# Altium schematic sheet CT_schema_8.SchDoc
size 391 x 238 mm
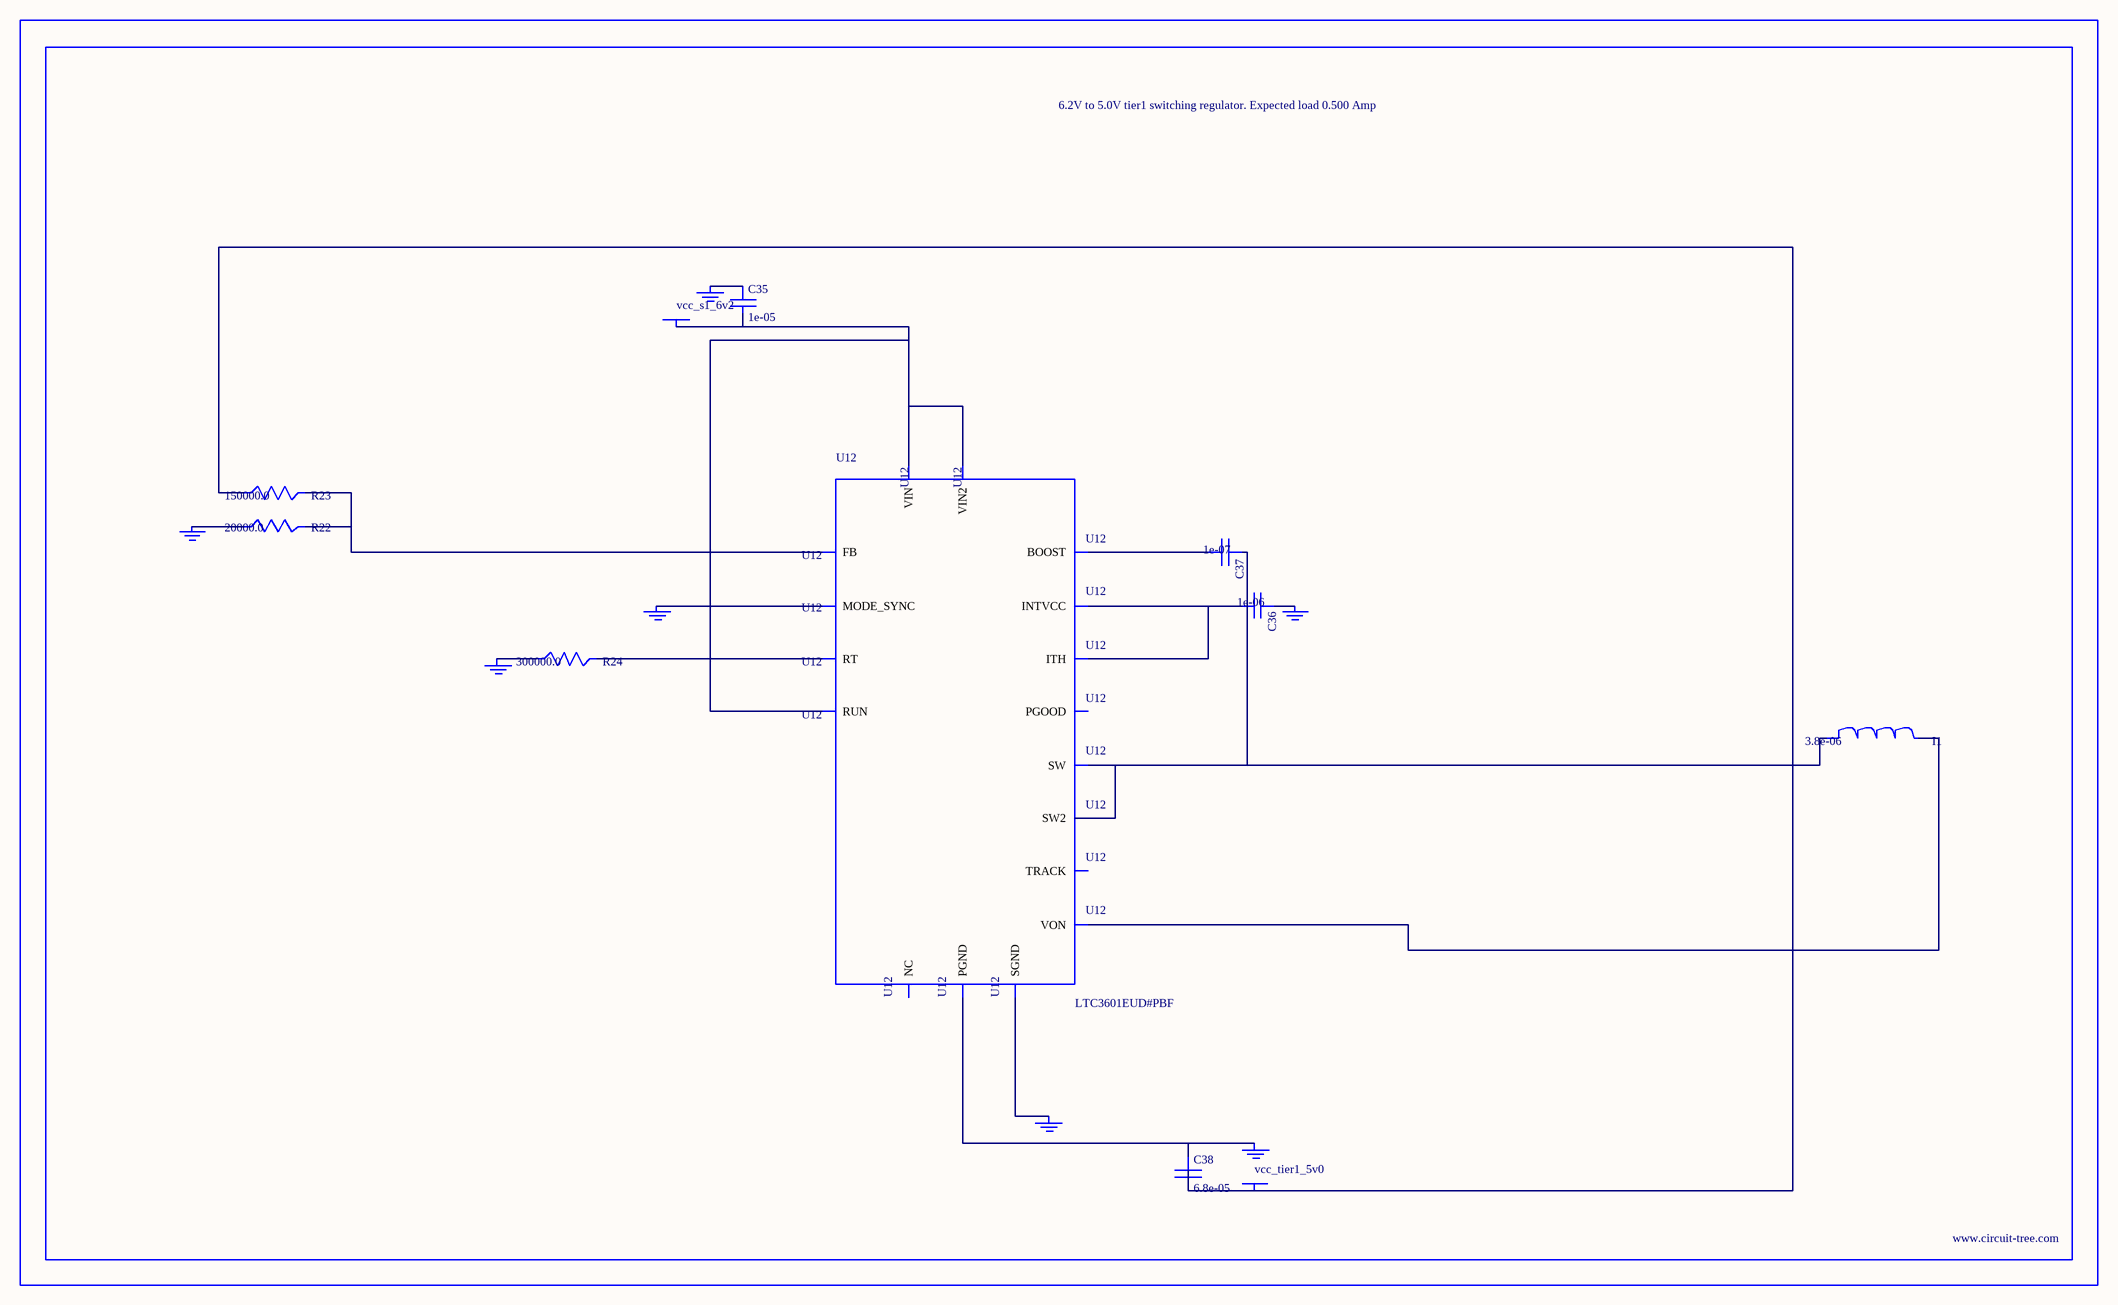
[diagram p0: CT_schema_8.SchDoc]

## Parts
BORDER7  (no value)
C35  1e-05  [C0805]
C36  1e-06  [C0603]
C37  1e-07  [C0402]
C38  6.8e-05  [2220]
GND_INSTANCE_7_0  (no value)
GND_INSTANCE_7_1  (no value)
GND_INSTANCE_7_2  (no value)
GND_INSTANCE_7_3  (no value)
GND_INSTANCE_7_4  (no value)
GND_INSTANCE_7_5  (no value)
GND_INSTANCE_7_6  (no value)
I1  3.8e-06  [DR1040]
POWER_INSTANCE_7_0  vcc_s1_6v2
POWER_INSTANCE_7_1  vcc_tier1_5v0
R22  20000.0  [R0603]
R23  150000.0  [R0603]
R24  300000.0  [R0603]
U12  LTC3601EUD#PBF  [QFN-16_EP]

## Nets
NetC35_1: C35.1 GND_INSTANCE_7_5.0(GND)
NetC35_2: C35.2 POWER_INSTANCE_7_0.0(PWR) U12.14(RUN) U12.15(VIN) U12.16(VIN2)
NetC36_1: C36.1 GND_INSTANCE_7_1.0(GND)
NetC36_2: C36.2 U12.7(INTVCC) U12.12(ITH)
NetC37_1: C37.1 I1.1 U12.3(SW) U12.4(SW2)
NetC37_2: C37.2 U12.6(BOOST)
NetC38_1: C38.1 GND_INSTANCE_7_6.0(GND) U12.17(PGND)
NetC38_2: C38.2 I1.2 POWER_INSTANCE_7_1.0(PWR) R23.1 U12.8(VON)
NetGND_INSTANCE_7_0_0: GND_INSTANCE_7_0.0(GND) U12.1(MODE_SYNC)
NetGND_INSTANCE_7_2_0: GND_INSTANCE_7_2.0(GND) U12.9(SGND)
NetGND_INSTANCE_7_3_0: GND_INSTANCE_7_3.0(GND) R24.1
NetGND_INSTANCE_7_4_0: GND_INSTANCE_7_4.0(GND) R22.1
NetR22_2: R22.2 R23.2 U12.11(FB)
NetR24_2: R24.2 U12.10(RT)

Not connected (* = marked no-connect by the designer): U12 2(PGOOD) 5(NC) 13(TRACK)

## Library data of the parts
BORDER7 = BORDER_PAGE7
C35 = C0805C106K8RACTU
C36 = C0603C105K3RACTU
C37 = C0402C104K3RACTU
C38 = C5750X5R1A686M
GND_INSTANCE_7_0-GND_INSTANCE_7_6 = GND
I1 = DR1040-3R8-R
POWER_INSTANCE_7_0 POWER_INSTANCE_7_1 = PWR
R22 = RC0603JR-0720KL
R23 = RC0603JR-07150KL
R24 = RC0603JR-07300KL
